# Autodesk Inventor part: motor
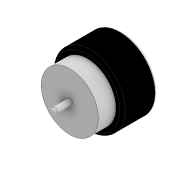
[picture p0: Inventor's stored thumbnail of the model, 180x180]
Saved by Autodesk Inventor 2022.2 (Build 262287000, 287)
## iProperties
Created: 2022-03
Part Number: motor
Material: Generic
Document SubType Name: Modeling
Designer: OHIL G H
Density: 1 g/cm^3
Appearance: Default
Author: OHIL G H
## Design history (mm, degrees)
sketch "Sketch1"
  geometry: C1 r 40 at (0, 0); 1 further point
  constraints: 1 centre point, 1 coincident
  dimensions: "d0" = 80 diameter of C1
extrude "Extrusion1" new body sketch "Sketch1" distance "d1" = 40; taper "d2" = 0 deg
sketch "Sketch2"
  geometry: C1 r 32.5 at (0, 0); 1 further point
  constraints: 1 centre point, 1 coincident
  dimensions: "d3" = 65 diameter of C1
extrude "Extrusion2" join sketch "Sketch2" distance "d4" = 20; taper "d5" = 0 deg
sketch "Sketch3"
  geometry: C1 r 3 at (0, 0); 1 further point
  constraints: 1 centre point, 1 coincident
  dimensions: "d6" = 6 diameter of C1
extrude "Extrusion3" join sketch "Sketch3" distance "d7" = 6; taper "d8" = 0 deg
fillet "Fillet1" dims "d9" = 2
sketch "Sketch4"
  geometry: C1 r 3 at (0, 0); 1 further point
  constraints: 1 centre point, 1 coincident
  dimensions: "d10" = 6 diameter of C1
extrude "Extrusion4" join sketch "Sketch4" distance "d11" = 20; taper "d12" = 0 deg
fillet "Fillet2" dims "d13" = 3
fillet "Fillet3" dims "d14" = 3
fillet "Fillet4" dims "d15" = 3
body "Solid1"
